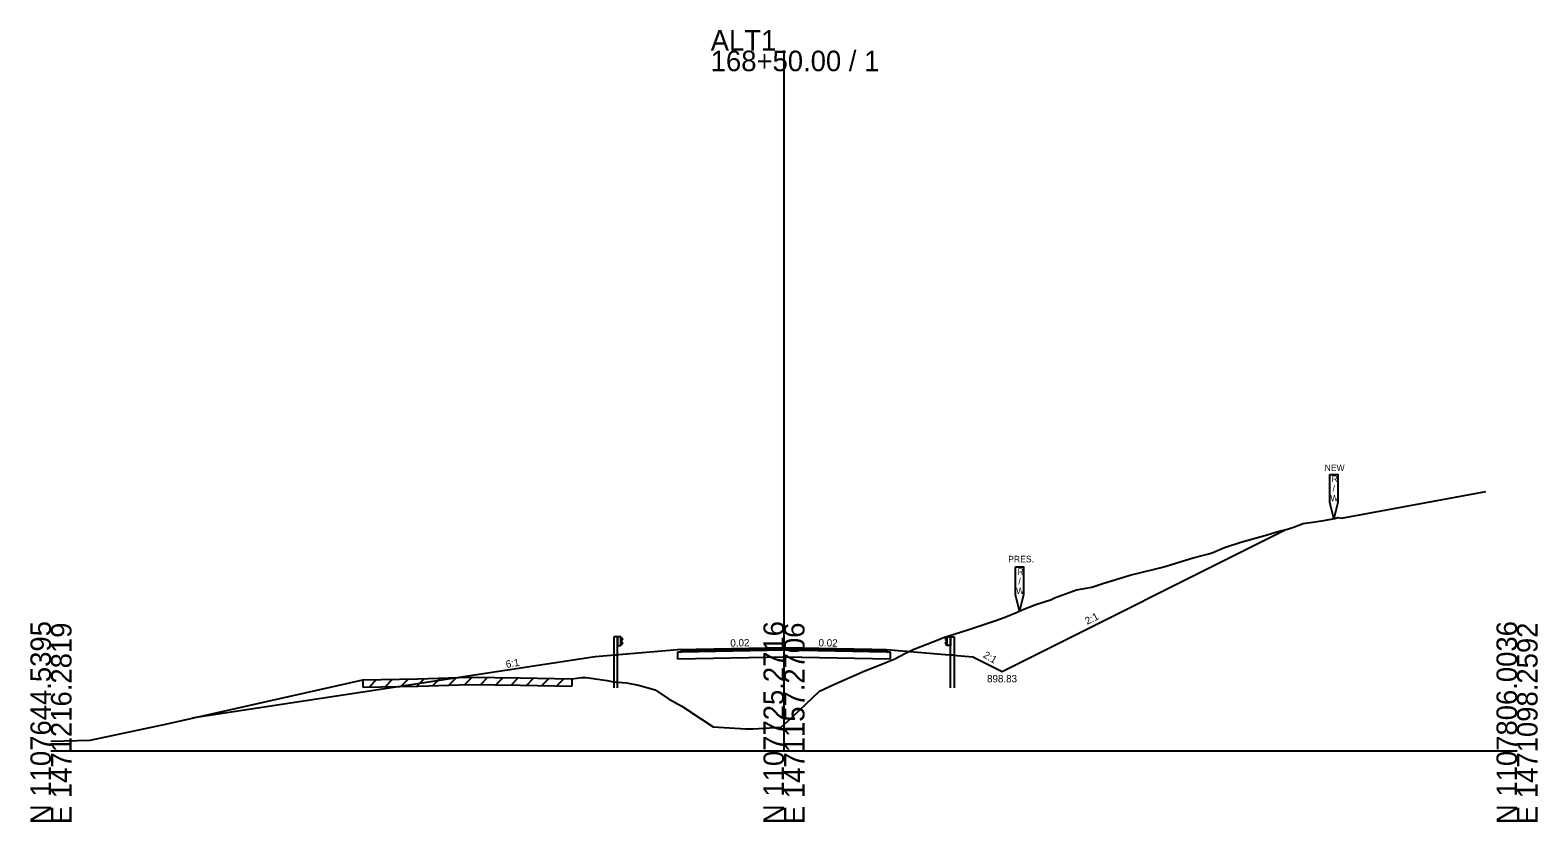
# Model space of a CAD drawing. Extents: x -26 to 2203, y -10 to 19568.
# Drawn here: x 997.2 to 1202.8, y 10490.3 to 10598.3 of the extents above; entities that cross this region are included whole.
import ezdxf

# ---------------------------------------------------------------- set-up
doc = ezdxf.new("R2010")
doc.units = 0
for name, color, linetype in [('RD_GPK_XS_Cell', 7, 'Continuous'), ('RD_XS_Base', 7, 'Continuous'), ('RD_XS_ExGround', 7, 'Continuous'), ('RD_XS_ExPaveRet', 7, 'Continuous'), ('RD_XS_ExRW', 7, 'Continuous'), ('RD_XS_GR', 7, 'Continuous'), ('RD_XS_Greenside', 7, 'Continuous'), ('RD_XS_NewRW', 7, 'Continuous'), ('RD_XS_Pave', 7, 'Continuous'), ('RD_XS_TieSlope', 7, 'Continuous'), ('RD_XS_TX_Slope', 7, 'Continuous')]:
    doc.layers.add(name, color=color, linetype=linetype)

msp = doc.modelspace()

# ---------------------------------------------------------------- linework, layer by layer
at = {"layer": 'RD_GPK_XS_Cell'}
for p, q in [((1100, 10500), (1100, 10595.48)), ((1000, 10500), (1100, 10500)), ((1100, 10500), (1200, 10500))]:
    msp.add_line(p, q, dxfattribs=at)
at = {"layer": 'RD_XS_Base'}
for points in [[(1085.5, 10513.49), (1086, 10513.5), (1100, 10513.78), (1114, 10513.5), (1114.5, 10513.49)], [(1085.5, 10512.49), (1085.5, 10513.49)], [(1114.5, 10512.49), (1100, 10512.78), (1085.5, 10512.49)], [(1114.5, 10513.49), (1114.5, 10512.49)]]:
    msp.add_lwpolyline(points, dxfattribs=at)
at = {"layer": 'RD_XS_ExGround'}
msp.add_line((1176.05, 10531.72), (1195.73, 10535.34), dxfattribs=at)
msp.add_lwpolyline([(1000, 10501.29), (1003.59, 10501.4), (1005.36, 10501.43), (1015.83, 10503.67), (1042.54, 10509.66), (1050.05, 10509.83), (1057.04, 10510.03), (1064.04, 10509.93), (1071.04, 10509.83), (1072.44, 10510.01), (1073.03, 10509.98), (1075.89, 10509.56), (1076.75, 10509.42), (1078.53, 10509.25), (1080.16, 10508.95), (1082.41, 10508.33), (1084.26, 10507.08), (1086.04, 10506.06), (1088.6, 10504.4), (1090.33, 10503.25), (1094.77, 10503.01), (1095.33, 10503), (1095.81, 10502.98), (1099.59, 10503.21), (1100, 10503.59), (1101.19, 10504.69), (1104.85, 10508.11), (1106.88, 10509.07), (1110.19, 10510.52), (1110.73, 10510.77), (1111.47, 10511.08), (1112.88, 10511.65), (1113.91, 10512.04), (1115.03, 10512.51), (1116.56, 10513.33), (1117.62, 10513.81), (1120.52, 10514.95), (1121.34, 10515.26), (1121.64, 10515.38), (1125.06, 10516.51), (1126.72, 10517.06), (1128.77, 10517.7), (1130.05, 10518.18), (1131.81, 10518.92), (1132.49, 10519.23), (1134.35, 10519.97), (1136.49, 10520.65), (1136.89, 10520.85), (1139.92, 10521.93), (1141.98, 10522.32), (1143.64, 10522.87), (1147.35, 10523.99), (1148.15, 10524.19), (1151.07, 10524.89), (1152.14, 10525.19), (1154.78, 10526.01), (1155.82, 10526.29), (1157.23, 10526.68), (1157.96, 10526.87), (1158.5, 10527.05), (1160.11, 10527.71), (1162.31, 10528.45), (1165.93, 10529.47), (1167.39, 10529.9), (1168.7, 10530.24), (1169.65, 10530.54), (1170.84, 10530.99), (1172.48, 10531.21), (1172.99, 10531.3), (1173.36, 10531.38), (1175.14, 10531.69), (1175.57, 10531.83), (1176.05, 10531.72)], dxfattribs=at)
at = {"layer": 'RD_XS_ExPaveRet'}
for p, q in [((1042.54, 10509.66), (1042.54, 10508.66)), ((1043.39, 10508.68), (1044.42, 10509.7)), ((1045.57, 10508.73), (1046.59, 10509.75)), ((1047.74, 10508.78), (1048.76, 10509.8)), ((1049.91, 10508.83), (1050.94, 10509.86)), ((1052.09, 10508.89), (1053.12, 10509.92)), ((1054.28, 10508.95), (1055.31, 10509.98)), ((1056.46, 10509.02), (1057.47, 10510.03)), ((1058.58, 10509.01), (1059.56, 10509.99)), ((1060.67, 10508.98), (1061.65, 10509.96)), ((1062.76, 10508.95), (1063.74, 10509.93)), ((1064.85, 10508.92), (1065.83, 10509.9)), ((1066.94, 10508.89), (1067.92, 10509.87)), ((1069.03, 10508.86), (1070.02, 10509.84)), ((1071.04, 10509.83), (1071.04, 10508.83))]:
    msp.add_line(p, q, dxfattribs=at)
msp.add_lwpolyline([(1042.54, 10508.66), (1050.08, 10508.83), (1057.05, 10509.03), (1064.02, 10508.93), (1071.04, 10508.83)], dxfattribs=at)
at = {"layer": 'RD_XS_ExRW'}
msp.add_lwpolyline([(1131.59, 10525.08), (1132.68, 10525.08), (1132.68, 10521.26), (1132.14, 10519.07), (1131.59, 10521.26)], close=True, dxfattribs=at)
at = {"layer": 'RD_XS_GR'}
for points in [[(1077.27, 10515.54), (1076.77, 10515.54)], [(1076.77, 10515.54), (1076.77, 10513.04)], [(1077.27, 10513.09), (1077.27, 10515.54)], [(1077.76, 10515.54), (1077.27, 10515.54)], [(1077.27, 10515.54), (1077.27, 10514.36)], [(1077.76, 10514.36), (1077.76, 10515.54)], [(1077.76, 10515.54), (1078, 10515.24)], [(1077.76, 10514.36), (1077.76, 10515.54)], [(1078, 10514.66), (1077.76, 10514.36)], [(1078, 10515.24), (1077.77, 10514.94)], [(1077.77, 10514.94), (1078, 10514.66)], [(1122.24, 10515.54), (1122, 10515.24)], [(1122, 10515.24), (1122.23, 10514.94)], [(1122.23, 10514.94), (1122, 10514.66)], [(1122, 10514.66), (1122.24, 10514.36)], [(1122.24, 10515.54), (1122.73, 10515.54)], [(1122.24, 10514.36), (1122.24, 10515.54)], [(1122.24, 10514.36), (1122.24, 10515.54)], [(1122.73, 10515.54), (1123.23, 10515.54)], [(1122.73, 10513.09), (1122.73, 10515.54)], [(1122.73, 10515.54), (1122.73, 10514.36)], [(1123.23, 10515.54), (1123.23, 10513.04)], [(1076.77, 10513.04), (1077.27, 10513.09)], [(1077.27, 10513.09), (1076.77, 10513.04)], [(1076.77, 10513.04), (1076.77, 10508.59)], [(1077.27, 10514.36), (1077.76, 10514.36)], [(1077.27, 10508.59), (1077.27, 10513.09)], [(1122.73, 10514.36), (1122.24, 10514.36)], [(1123.23, 10513.04), (1122.73, 10513.09)], [(1122.73, 10508.59), (1122.73, 10513.09)], [(1122.73, 10513.09), (1123.23, 10513.04)], [(1123.23, 10513.04), (1123.23, 10508.59)]]:
    msp.add_lwpolyline(points, dxfattribs=at)
at = {"layer": 'RD_XS_Greenside'}
msp.add_line((1125.75, 10512.83), (1127.75, 10511.83), dxfattribs=at)
for points in [[(1074.25, 10512.83), (1019.21, 10504.43)], [(1086, 10513.81), (1074.25, 10512.83)], [(1086, 10513.81), (1078, 10513.15)], [(1114, 10513.81), (1122, 10513.15)], [(1114, 10513.81), (1125.75, 10512.83)]]:
    msp.add_lwpolyline(points, dxfattribs=at)
at = {"layer": 'RD_XS_NewRW'}
msp.add_lwpolyline([(1174.45, 10537.68), (1175.55, 10537.68), (1175.55, 10533.85), (1175, 10531.66), (1174.45, 10533.85)], close=True, dxfattribs=at)
at = {"layer": 'RD_XS_Pave'}
for points in [[(1086, 10513.81), (1088, 10513.85), (1100, 10514.09), (1112, 10513.85), (1114, 10513.81)], [(1086, 10513.65), (1100, 10513.93), (1114, 10513.65)], [(1114, 10513.65), (1100, 10513.93), (1086, 10513.65)], [(1086, 10513.65), (1086, 10513.81)], [(1114, 10513.5), (1100, 10513.78), (1086, 10513.5)], [(1086, 10513.5), (1086, 10513.65)], [(1114, 10513.81), (1114, 10513.65)], [(1114, 10513.65), (1114, 10513.5)]]:
    msp.add_lwpolyline(points, dxfattribs=at)
at = {"layer": 'RD_XS_TieSlope'}
msp.add_line((1125.75, 10512.83), (1129.75, 10510.83), dxfattribs=at)
msp.add_lwpolyline([(1129.75, 10510.83), (1168.45, 10530.18)], dxfattribs=at)

# ---------------------------------------------------------------- texts
at = {"layer": 'RD_GPK_XS_Cell'}
for s, p in [('ALT1', (1090, 10595.48)), ('168+50.00 / 1', (1090, 10592.68))]:
    msp.add_text(s, height=2.8, dxfattribs=at).set_placement(p)
for s, p in [('N 1107644.5395', (1000, 10490)), ('E 1471216.2819', (1002.8, 10490)), ('N 1107725.2716', (1100, 10490)), ('E 1471157.2706', (1102.8, 10490)), ('N 1107806.0036', (1200, 10490)), ('E 1471098.2592', (1202.8, 10490))]:
    msp.add_text(s, height=2.8, rotation=90, dxfattribs=at).set_placement(p)
at = {"layer": 'RD_XS_ExRW'}
for s, p in [('PRES.', (1130.59, 10525.71)), ('R', (1131.85, 10523.99)), ('/', (1131.97, 10522.68)), ('W', (1131.67, 10521.37))]:
    msp.add_text(s, height=0.875, dxfattribs=at).set_placement(p)
at = {"layer": 'RD_XS_NewRW'}
for s, p in [('NEW', (1173.75, 10538.16)), ('R', (1174.71, 10536.64)), ('/', (1174.83, 10535.33)), ('W', (1174.53, 10534.02))]:
    msp.add_text(s, height=0.875, dxfattribs=at).set_placement(p)
at = {"layer": 'RD_XS_TX_Slope'}
for s, rotation, p in [('2:1', 26.5651, (1141.37, 10517.16)), ('0.02', 1.1458, (1092.69, 10514.2)), ('0.02', 358.8542, (1104.7, 10514.25)), ('6:1', 9.4642, (1062.13, 10511.29)), ('2:1', 329.0708, (1127.08, 10512.8))]:
    msp.add_text(s, height=1, rotation=rotation, dxfattribs=at).set_placement(p)
msp.add_text('898.83', height=1, dxfattribs=at).set_placement((1127.7, 10509.33))

doc.saveas('drawing.dxf')
